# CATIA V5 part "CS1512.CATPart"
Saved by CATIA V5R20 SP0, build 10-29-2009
Part number: CS1512
Revision: 4
Definition: design
Nomenclature: CS1512
Source: made
Description: NOT SPECIFIED
Bounding box of the stored display mesh (mm): x -11.818 to 12, y -12 to 12, z -22 to 6
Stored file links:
  C:\Users\Raffaele\Desktop\3D X SITO CF\BOLEX\20-TILTED COLUMN SUPPORT\CS1512.CATPart
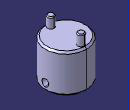
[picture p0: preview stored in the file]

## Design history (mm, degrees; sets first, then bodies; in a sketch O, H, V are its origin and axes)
Body1 "MANIFOLD_SOLID_BREP #683" (main body)
  Solid1: solid without history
